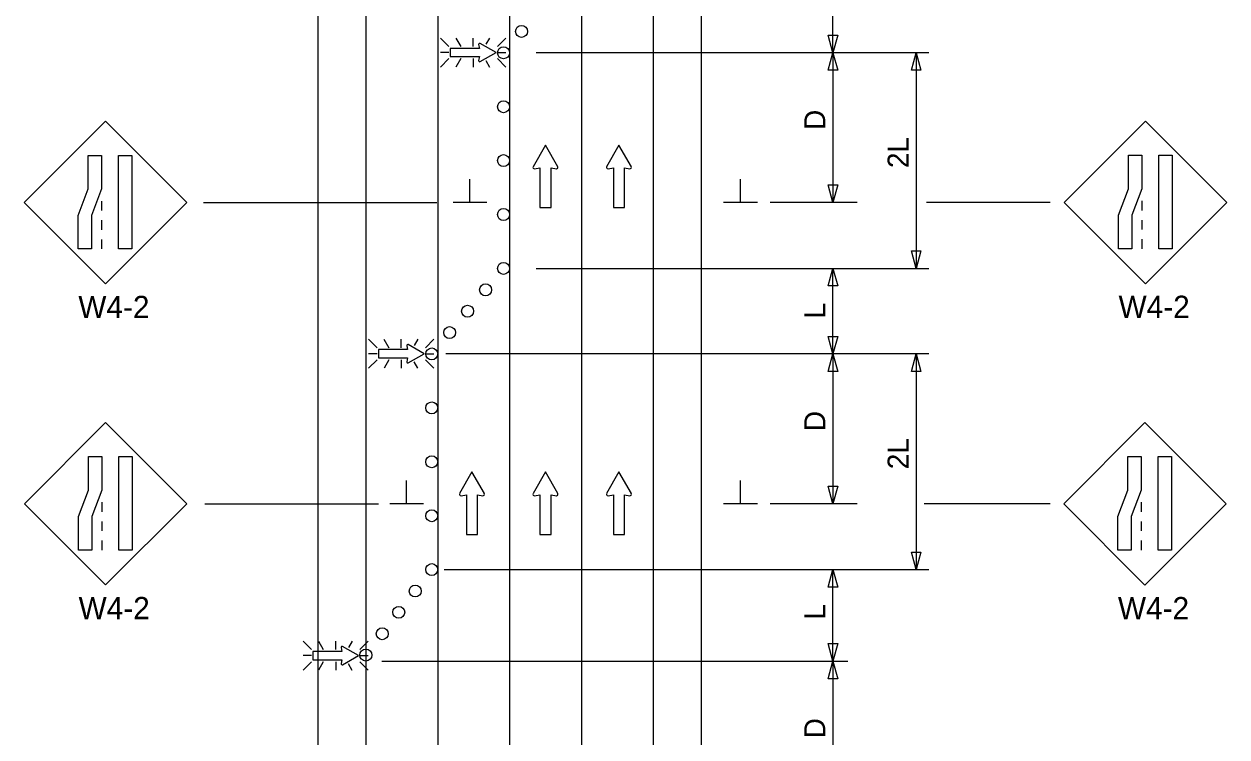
# Model space of a CAD drawing. Extents: x 16730 to 18479, y 5752 to 6927.
# Drawn here: x 16781.6 to 17183.3, y 6433 to 6671 of the extents above; entities that cross this region are included whole.
import ezdxf

# ---------------------------------------------------------------- set-up
doc = ezdxf.new("R2010")
doc.units = 0
for name, color, linetype in [('ALI_LEGAL_EX', 7, 'Continuous'), ('MT_SCRATCH_LEVEL_E', 7, 'Continuous'), ('PAVT_EDGE_EX', 7, 'Continuous'), ('TRAFFIC_SIGNS_PR', 7, 'Continuous'), ('TYPICAL_TEXT_DIMEN_PR', 7, 'Continuous')]:
    doc.layers.add(name, color=color, linetype=linetype)

msp = doc.modelspace()

# ---------------------------------------------------------------- linework, layer by layer
at = {"layer": 'ALI_LEGAL_EX'}
for p, q in [((16919.74, 6876.43), (16919.74, 5996.39)), ((16943.74, 6876.43), (16943.74, 5996.39)), ((16967.74, 6876.43), (16967.74, 5996.39))]:
    msp.add_line(p, q, dxfattribs=at)
for points in [[(16919.74, 6596.46), (16919.74, 6571.46)], [(16967.74, 6596.46), (16967.74, 6571.46)], [(16943.74, 6496.46), (16943.74, 6471.46)], [(16967.74, 6496.46), (16967.74, 6471.46)]]:
    msp.add_lwpolyline(points, dxfattribs=at)
at = {"layer": 'MT_SCRATCH_LEVEL_E'}
for p, q in [((16955.7, 6630.62), (16951.59, 6623.38)), ((16959.85, 6623.38), (16955.7, 6630.62)), ((16980.26, 6630.62), (16976.15, 6623.38)), ((16984.41, 6623.38), (16980.26, 6630.62)), ((16952.08, 6622.7), (16953.85, 6623.02)), ((16953.85, 6623.02), (16953.85, 6609.76)), ((16957.59, 6609.76), (16957.59, 6623.02)), ((16957.59, 6623.02), (16959.37, 6622.7)), ((16976.63, 6622.7), (16978.41, 6623.02)), ((16978.41, 6623.02), (16978.41, 6609.76)), ((16982.15, 6609.76), (16982.15, 6623.02)), ((16982.15, 6623.02), (16983.93, 6622.7)), ((16953.85, 6609.76), (16957.59, 6609.76)), ((16978.41, 6609.76), (16982.15, 6609.76)), ((16931.18, 6521.46), (16927.06, 6514.22)), ((16935.32, 6514.22), (16931.18, 6521.46)), ((16955.7, 6521.46), (16951.59, 6514.22)), ((16959.85, 6514.22), (16955.7, 6521.46)), ((16980.26, 6521.46), (16976.15, 6514.22)), ((16984.41, 6514.22), (16980.26, 6521.46)), ((16927.55, 6513.53), (16929.32, 6513.85)), ((16929.32, 6513.85), (16929.32, 6500.59)), ((16933.07, 6500.59), (16933.07, 6513.85)), ((16933.07, 6513.85), (16934.84, 6513.53)), ((16952.08, 6513.53), (16953.85, 6513.85)), ((16953.85, 6513.85), (16953.85, 6500.59)), ((16957.59, 6500.59), (16957.59, 6513.85)), ((16957.59, 6513.85), (16959.37, 6513.53)), ((16976.63, 6513.53), (16978.41, 6513.85)), ((16978.41, 6513.85), (16978.41, 6500.59)), ((16982.15, 6500.59), (16982.15, 6513.85)), ((16982.15, 6513.85), (16983.93, 6513.53)), ((16929.32, 6500.59), (16933.07, 6500.59)), ((16953.85, 6500.59), (16957.59, 6500.59)), ((16978.41, 6500.59), (16982.15, 6500.59))]:
    msp.add_line(p, q, dxfattribs=at)
for centre, start, end in [((16952, 6623.16), 150.4248, 279.9638), ((16959.44, 6623.16), 260.0362, 29.7731), ((16976.56, 6623.16), 150.4248, 279.9638), ((16984, 6623.16), 260.0362, 29.7731), ((16927.47, 6513.99), 150.4248, 279.9638), ((16934.91, 6513.99), 260.0362, 29.7731), ((16952, 6513.99), 150.4248, 279.9638), ((16959.44, 6513.99), 260.0362, 29.7731), ((16976.56, 6513.99), 150.4248, 279.9638), ((16984, 6513.99), 260.0362, 29.7731)]:
    msp.add_arc(centre, 0.463, start, end, dxfattribs=at)
at = {"layer": 'PAVT_EDGE_EX'}
for p, q in [((16879.74, 6926.69), (16879.74, 6016.42)), ((16895.74, 6926.69), (16895.74, 6016.42)), ((16991.74, 6926.69), (16991.74, 6016.42)), ((17007.74, 6926.69), (17007.74, 6016.42))]:
    msp.add_line(p, q, dxfattribs=at)
at = {"layer": 'TRAFFIC_SIGNS_PR'}
for p, q in [((16923.51, 6663.52), (16920.69, 6666.34)), ((16925.81, 6666.34), (16927.44, 6663.52)), ((16931.6, 6663.52), (16931.6, 6666.34)), ((16937.07, 6666.34), (16935.86, 6664.25)), ((16942.5, 6666.34), (16939.68, 6663.52)), ((16923.51, 6661.49), (16920.69, 6661.49)), ((16939.68, 6661.49), (16942.5, 6661.49)), ((16923.51, 6659.46), (16920.69, 6656.64)), ((16927.46, 6659.46), (16925.83, 6656.64)), ((16931.6, 6659.46), (16931.6, 6656.64)), ((16935.78, 6658.82), (16937.04, 6656.64)), ((16942.5, 6656.64), (16939.68, 6659.46)), ((16808.77, 6638.57), (16781.61, 6611.42)), ((16835.92, 6611.42), (16808.77, 6638.57)), ((17156.15, 6638.63), (17129, 6611.48)), ((17183.3, 6611.48), (17156.15, 6638.63)), ((16807.52, 6611.91), (16807.52, 6608.71)), ((17154.9, 6611.97), (17154.9, 6608.77)), ((16781.61, 6611.42), (16808.77, 6584.26)), ((16808.77, 6584.26), (16835.92, 6611.42)), ((17129, 6611.48), (17156.15, 6584.32)), ((17156.15, 6584.32), (17183.3, 6611.48)), ((16807.52, 6605.51), (16807.52, 6602.31)), ((17154.9, 6605.57), (17154.9, 6602.37)), ((16807.52, 6599.11), (16807.52, 6595.91)), ((17154.9, 6599.17), (17154.9, 6595.97)), ((16899.51, 6562.96), (16896.69, 6565.78)), ((16901.81, 6565.78), (16903.44, 6562.96)), ((16907.6, 6562.96), (16907.6, 6565.78)), ((16913.07, 6565.78), (16911.86, 6563.69)), ((16918.5, 6565.78), (16915.68, 6562.96)), ((16899.51, 6560.93), (16896.69, 6560.93)), ((16915.68, 6560.93), (16918.5, 6560.93)), ((16899.51, 6558.89), (16896.69, 6556.07)), ((16903.46, 6558.89), (16901.83, 6556.07)), ((16907.6, 6558.89), (16907.6, 6556.07)), ((16911.78, 6558.26), (16913.04, 6556.07)), ((16918.5, 6556.08), (16915.68, 6558.89)), ((16808.86, 6538.03), (16781.71, 6510.88)), ((16836.01, 6510.88), (16808.86, 6538.03)), ((17155.94, 6538.02), (17128.79, 6510.87)), ((17183.1, 6510.87), (17155.94, 6538.02)), ((16781.71, 6510.88), (16808.86, 6483.73)), ((16807.61, 6511.37), (16807.61, 6508.17)), ((16808.86, 6483.73), (16836.01, 6510.88)), ((17128.79, 6510.87), (17155.94, 6483.71)), ((17154.7, 6511.36), (17154.7, 6508.16)), ((17155.94, 6483.71), (17183.1, 6510.87)), ((16807.61, 6504.97), (16807.61, 6501.77)), ((17154.7, 6504.96), (17154.7, 6501.76)), ((16807.61, 6498.57), (16807.61, 6495.37)), ((17154.7, 6498.56), (17154.7, 6495.36)), ((16877.59, 6462.17), (16874.77, 6464.99)), ((16879.89, 6464.99), (16881.52, 6462.17)), ((16885.68, 6462.17), (16885.68, 6464.99)), ((16891.14, 6464.99), (16889.94, 6462.89)), ((16896.58, 6464.99), (16893.76, 6462.17)), ((16877.59, 6460.14), (16874.77, 6460.14)), ((16893.76, 6460.14), (16896.58, 6460.14)), ((16877.59, 6458.1), (16874.77, 6455.28)), ((16881.54, 6458.1), (16879.91, 6455.28)), ((16885.68, 6458.1), (16885.68, 6455.28)), ((16889.86, 6457.47), (16891.12, 6455.28)), ((16896.58, 6455.28), (16893.76, 6458.1))]:
    msp.add_line(p, q, dxfattribs=at)
for points in [[(16933.42, 6664.17), (16933.65, 6662.88), (16923.93, 6662.88), (16923.93, 6660.13), (16933.65, 6660.13), (16933.42, 6658.83)], [(16933.92, 6658.47), (16939.23, 6661.49), (16933.92, 6664.53)], [(16909.92, 6557.91), (16915.23, 6560.93), (16909.92, 6563.97)], [(16909.42, 6563.61), (16909.65, 6562.31), (16899.93, 6562.31), (16899.93, 6559.57), (16909.65, 6559.57), (16909.42, 6558.27)], [(16887.5, 6462.82), (16887.73, 6461.52), (16878.01, 6461.52), (16878.01, 6458.78), (16887.73, 6458.78), (16887.5, 6457.47)], [(16888, 6457.12), (16893.31, 6460.14), (16888, 6463.18)]]:
    msp.add_lwpolyline(points, dxfattribs=at)
for points in [[(16807.52, 6627.15), (16807.52, 6615.97), (16804.18, 6607.09), (16804.18, 6595.91), (16799.68, 6595.91), (16799.68, 6607.09), (16803.03, 6615.97), (16803.03, 6627.15)], [(16817.66, 6627.15), (16817.66, 6595.91), (16813.16, 6595.91), (16813.16, 6627.15)], [(17154.9, 6627.21), (17154.9, 6616.03), (17151.56, 6607.15), (17151.56, 6595.97), (17147.07, 6595.97), (17147.07, 6607.15), (17150.41, 6616.03), (17150.41, 6627.21)], [(17165.04, 6627.21), (17165.04, 6595.97), (17160.55, 6595.97), (17160.55, 6627.21)], [(16807.61, 6526.61), (16807.61, 6515.43), (16804.27, 6506.55), (16804.27, 6495.37), (16799.77, 6495.37), (16799.77, 6506.55), (16803.12, 6515.43), (16803.12, 6526.61)], [(16817.75, 6526.61), (16817.75, 6495.37), (16813.25, 6495.37), (16813.25, 6526.61)], [(17154.7, 6526.6), (17154.7, 6515.42), (17151.35, 6506.54), (17151.35, 6495.36), (17146.86, 6495.36), (17146.86, 6506.54), (17150.2, 6515.42), (17150.2, 6526.6)], [(17164.83, 6526.6), (17164.83, 6495.36), (17160.34, 6495.36), (17160.34, 6526.6)]]:
    msp.add_lwpolyline(points, close=True, dxfattribs=at)
for centre in [(16947.74, 6668.56), (16941.74, 6661.42), (16941.74, 6643.42), (16941.74, 6625.42), (16941.74, 6607.42), (16941.74, 6589.42), (16935.74, 6582.28), (16929.74, 6575.14), (16923.74, 6568), (16917.74, 6560.86), (16917.74, 6542.86), (16917.74, 6524.86), (16917.74, 6506.86), (16917.74, 6488.86), (16912.24, 6481.72), (16906.74, 6474.6), (16901.24, 6467.47), (16895.75, 6460.34)]:
    msp.add_circle(centre, 2, dxfattribs=at)
for centre, start, end in [((16933.76, 6664.23), 61.4833, 189.9593), ((16933.76, 6658.77), 170.7308, 298.8916), ((16909.76, 6563.67), 61.4833, 189.9593), ((16909.76, 6558.21), 170.7308, 298.8916), ((16887.84, 6462.88), 61.4833, 189.9593), ((16887.84, 6457.42), 170.7308, 298.8916)]:
    msp.add_arc(centre, 0.341, start, end, dxfattribs=at)
at = {"layer": 'TYPICAL_TEXT_DIMEN_PR'}
for p, q in [((17051.74, 6661.42), (17051.74, 6691.98)), ((17051.74, 6661.42), (17050.17, 6667.28)), ((17050.17, 6667.28), (17051.74, 6667.28)), ((17051.74, 6667.28), (17053.31, 6667.28)), ((17053.31, 6667.28), (17051.74, 6661.42)), ((17083.78, 6661.42), (16952.64, 6661.42)), ((17050.17, 6655.56), (17051.74, 6661.42)), ((17051.74, 6661.42), (17051.74, 6611.42)), ((17051.74, 6661.42), (17053.31, 6655.56)), ((17077.97, 6655.56), (17079.54, 6661.42)), ((17079.54, 6661.42), (17081.11, 6655.56)), ((17079.54, 6661.42), (17079.54, 6589.42)), ((17051.74, 6655.56), (17050.17, 6655.56)), ((17053.31, 6655.56), (17051.74, 6655.56)), ((17079.54, 6655.56), (17077.97, 6655.56)), ((17081.11, 6655.56), (17079.54, 6655.56)), ((16930.53, 6611.42), (16930.53, 6619.2)), ((17020.86, 6611.42), (17020.86, 6619.2)), ((17051.74, 6611.42), (17050.17, 6617.28)), ((17050.17, 6617.28), (17051.74, 6617.28)), ((17051.74, 6617.28), (17053.31, 6617.28)), ((17053.31, 6617.28), (17051.74, 6611.42)), ((17079.54, 6616.29), (17079.54, 6612.52)), ((16841.52, 6611.42), (16919.49, 6611.42)), ((16936.16, 6611.42), (16924.91, 6611.42)), ((17026.49, 6611.42), (17015.24, 6611.42)), ((17059.87, 6611.42), (17030.74, 6611.42)), ((17124.29, 6611.42), (17082.94, 6611.42)), ((17079.54, 6589.42), (17077.97, 6595.28)), ((17077.97, 6595.28), (17079.54, 6595.28)), ((17079.54, 6595.28), (17081.11, 6595.28)), ((17081.11, 6595.28), (17079.54, 6589.42)), ((16952.64, 6589.42), (17083.78, 6589.42)), ((17050.17, 6583.56), (17051.74, 6589.42)), ((17051.74, 6560.86), (17051.74, 6589.42)), ((17051.74, 6589.42), (17053.31, 6583.56)), ((17051.74, 6583.56), (17050.17, 6583.56)), ((17053.31, 6583.56), (17051.74, 6583.56)), ((17051.74, 6560.86), (17050.17, 6566.72)), ((17050.17, 6566.72), (17051.74, 6566.72)), ((17051.74, 6566.72), (17053.31, 6566.72)), ((17053.31, 6566.72), (17051.74, 6560.86)), ((17083.78, 6560.86), (16922.45, 6560.86)), ((17050.17, 6554.99), (17051.74, 6560.86)), ((17051.74, 6560.86), (17051.74, 6510.86)), ((17051.74, 6560.86), (17053.31, 6554.99)), ((17077.97, 6554.99), (17079.54, 6560.86)), ((17079.54, 6560.86), (17081.11, 6554.99)), ((17079.54, 6560.86), (17079.54, 6488.86)), ((17051.74, 6554.99), (17050.17, 6554.99)), ((17053.31, 6554.99), (17051.74, 6554.99)), ((17079.54, 6554.99), (17077.97, 6554.99)), ((17081.11, 6554.99), (17079.54, 6554.99)), ((16909.37, 6510.86), (16909.37, 6518.64)), ((17020.86, 6510.86), (17020.86, 6518.64)), ((17051.74, 6510.86), (17050.17, 6516.72)), ((17050.17, 6516.72), (17051.74, 6516.72)), ((17051.74, 6516.72), (17053.31, 6516.72)), ((17053.31, 6516.72), (17051.74, 6510.86)), ((17079.54, 6515.73), (17079.54, 6511.96)), ((16841.94, 6510.86), (16899.93, 6510.86)), ((16915, 6510.86), (16903.75, 6510.86)), ((17026.49, 6510.86), (17015.24, 6510.86)), ((17059.87, 6510.86), (17030.74, 6510.86)), ((17124.29, 6510.86), (17082.22, 6510.86)), ((17079.54, 6488.86), (17077.97, 6494.72)), ((17077.97, 6494.72), (17079.54, 6494.72)), ((17079.54, 6494.72), (17081.11, 6494.72)), ((17081.11, 6494.72), (17079.54, 6488.86)), ((16921.92, 6488.86), (17083.78, 6488.86)), ((16952.64, 6488.86), (17083.78, 6488.86)), ((17050.17, 6482.99), (17051.74, 6488.86)), ((17051.74, 6458.29), (17051.74, 6488.86)), ((17051.74, 6488.86), (17053.31, 6482.99)), ((17051.74, 6482.99), (17050.17, 6482.99)), ((17053.31, 6482.99), (17051.74, 6482.99)), ((17051.74, 6458.29), (17050.17, 6464.15)), ((17050.17, 6464.15), (17051.74, 6464.15)), ((17051.74, 6464.15), (17053.31, 6464.15)), ((17053.31, 6464.15), (17051.74, 6458.29)), ((16901.05, 6458.29), (17056.74, 6458.29)), ((17050.17, 6452.43), (17051.74, 6458.29)), ((17051.74, 6458.29), (17051.74, 6408.29)), ((17051.74, 6458.29), (17053.31, 6452.43)), ((17051.74, 6452.43), (17050.17, 6452.43)), ((17053.31, 6452.43), (17051.74, 6452.43))]:
    msp.add_line(p, q, dxfattribs=at)

# ---------------------------------------------------------------- texts
at = {"layer": 'TRAFFIC_SIGNS_PR'}
for p in [(16799.73, 6572.83), (17147.11, 6572.88), (16799.82, 6472.29), (17146.9, 6472.27)]:
    msp.add_text('W4-2', height=7.44, dxfattribs=at).set_placement(p)
at = {"layer": 'TYPICAL_TEXT_DIMEN_PR'}
for s, p in [('D', (17049.18, 6635.64)), ('2L', (17076.98, 6622.92)), ('L', (17049.18, 6572.71)), ('D', (17049.18, 6535.07)), ('2L', (17076.98, 6522.36)), ('L', (17049.18, 6472.15)), ('D', (17049.18, 6432.51))]:
    msp.add_text(s, height=7, rotation=90, dxfattribs=at).set_placement(p)

doc.saveas('drawing.dxf')
